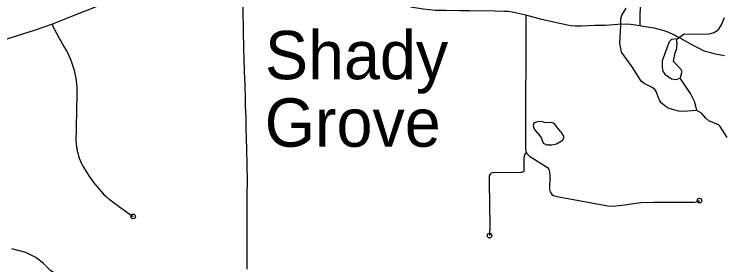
# Model space of a CAD drawing. Extents: x -19 to 366, y -4 to 359.
# Drawn here: x 143.314 to 144.78, y 191.501 to 192.02 of the extents above; entities that cross this region are included whole.
import ezdxf

# ---------------------------------------------------------------- set-up
doc = ezdxf.new("R2010")
doc.units = 0
for name, color, linetype in [('Level 24', 7, 'Continuous'), ('Level 31', 7, 'Continuous'), ('Level 32', 7, 'Continuous'), ('Level 35', 7, 'Continuous'), ('Level 60', 7, 'Continuous')]:
    doc.layers.add(name, color=color, linetype=linetype)

msp = doc.modelspace()

# ---------------------------------------------------------------- linework, layer by layer
at = {"layer": 'Level 31'}
for points in [[(143.785, 192.1059), (143.7855, 192.0918), (143.7865, 192.0521), (143.7867, 192.0267), (143.7881, 191.9466), (143.7888, 191.9291), (143.7894, 191.901)], [(143.4977, 192.041), (143.4828, 192.0352), (143.4289, 192.0136), (143.3943, 192.0002), (143.3929, 191.9996)], [(144.3723, 192.0176), (144.3536, 192.0224), (144.3441, 192.0243), (144.3355, 192.0253), (144.3281, 192.0257), (144.3077, 192.0261), (144.2556, 192.0267), (144.235, 192.0272), (144.2071, 192.0276), (144.1852, 192.0279), (144.1726, 192.0287), (144.1597, 192.0301), (144.1385, 192.0339), (144.126, 192.0374), (144.1074, 192.0433)], [(144.3723, 192.0176), (144.3714, 191.7521), (144.3715, 191.7421)], [(144.7833, 191.9338), (144.7642, 191.9375), (144.755, 191.9397), (144.7441, 191.9428), (144.7384, 191.9451), (144.7321, 191.948), (144.7186, 191.9549), (144.6915, 191.9702), (144.6833, 191.9747), (144.6799, 191.9765), (144.6682, 191.9822), (144.6585, 191.9857), (144.6478, 191.9885), (144.6379, 191.9908), (144.6143, 191.9947), (144.6071, 191.996), (144.5948, 191.998), (144.5885, 191.9989), (144.5803, 191.999), (144.5622, 191.9984), (144.5368, 191.9969), (144.527, 191.9967), (144.5149, 191.9963), (144.4873, 191.9949), (144.4811, 191.9949), (144.4743, 191.9953), (144.4659, 191.9962), (144.4584, 191.9974), (144.4353, 192.002), (144.4208, 192.0052), (144.4051, 192.009), (144.3723, 192.0176)], [(143.3929, 191.9996), (143.3568, 191.9872), (143.236, 191.9493)], [(143.3929, 191.9996), (143.3927, 191.9957), (143.4058, 191.9714), (143.4163, 191.9529), (143.4228, 191.9418), (143.4307, 191.9247), (143.4351, 191.9126), (143.4369, 191.9065), (143.4385, 191.9003), (143.4398, 191.8941), (143.4409, 191.8879), (143.4426, 191.8756), (143.4427, 191.8752), (143.4429, 191.8701), (143.443, 191.8649), (143.443, 191.8594), (143.443, 191.8519), (143.4428, 191.8421), (143.4426, 191.8331), (143.4415, 191.7741), (143.4414, 191.7669), (143.4414, 191.7611), (143.4414, 191.7581), (143.4415, 191.7558), (143.4417, 191.7526), (143.4419, 191.7505), (143.4423, 191.7474), (143.4426, 191.7445), (143.4431, 191.7418), (143.4436, 191.7384), (143.4441, 191.7364), (143.4449, 191.733), (143.4459, 191.7297), (143.4466, 191.727), (143.4482, 191.7223), (143.4502, 191.717), (143.4522, 191.7125), (143.4543, 191.708), (143.4566, 191.7037), (143.4588, 191.6999), (143.4622, 191.6946), (143.4658, 191.6892), (143.4695, 191.6837), (143.474, 191.6771), (143.4778, 191.6719), (143.4822, 191.6662), (143.4857, 191.6618), (143.4897, 191.6572), (143.4939, 191.6527), (143.4986, 191.6479), (143.5036, 191.6431), (143.5099, 191.6375), (143.5148, 191.6336), (143.521, 191.6289), (143.5279, 191.624), (143.5343, 191.6195), (143.5407, 191.615), (143.5458, 191.6114), (143.5598, 191.6017)], [(143.7894, 191.901), (143.7905, 191.8739), (143.7908, 191.8667), (143.7913, 191.8507), (143.7917, 191.8294), (143.7925, 191.8055), (143.7931, 191.7853), (143.7938, 191.7619), (143.7943, 191.7412), (143.7951, 191.7084), (143.7952, 191.673), (143.795, 191.6492), (143.7948, 191.6158), (143.7948, 191.6002), (143.7948, 191.5857), (143.7948, 191.5603), (143.7948, 191.5467), (143.7948, 191.4948), (143.7948, 191.4924)], [(144.3715, 191.7421), (144.3724, 191.7364), (144.3747, 191.7313), (144.3796, 191.7266), (144.4149, 191.7045), (144.4177, 191.7024), (144.4199, 191.6989), (144.4213, 191.6933), (144.4214, 191.6847), (144.4212, 191.6582), (144.4223, 191.6526), (144.4262, 191.647), (144.4296, 191.6448), (144.436, 191.6428), (144.4481, 191.6409), (144.5418, 191.6238), (144.5505, 191.6229), (144.5584, 191.6232), (144.5766, 191.6257), (144.5945, 191.6285), (144.6102, 191.6302), (144.6362, 191.6308), (144.7213, 191.6311), (144.728, 191.6325), (144.7314, 191.6344)], [(144.3733, 191.7343), (144.3694, 191.7294), (144.3676, 191.7228), (144.3676, 191.6988), (144.3676, 191.6961), (144.367, 191.6937), (144.3654, 191.6931), (144.3633, 191.6925), (144.3615, 191.6925), (144.3031, 191.6919), (144.3004, 191.691), (144.2983, 191.6892), (144.2964, 191.6858), (144.2964, 191.6816), (144.2964, 191.6719), (144.2973, 191.582), (144.297, 191.562)]]:
    msp.add_lwpolyline(points, dxfattribs=at)
for centre in [(144.7314, 191.6344), (143.5598, 191.6017), (144.297, 191.562)]:
    msp.add_circle(centre, 0.00473, dxfattribs=at)
at = {"layer": 'Level 32'}
msp.add_lwpolyline([(144.6088, 191.9957), (144.6097, 192.1166)], dxfattribs=at)
at = {"layer": 'Level 35'}
for points in [[(144.5922, 191.9109), (144.5702, 191.9416), (144.5666, 191.9598), (144.5687, 191.9968), (144.5688, 192.0102), (144.5704, 192.0177), (144.5798, 192.0325)], [(144.6853, 191.9687), (144.6994, 191.9795), (144.7121, 191.9784), (144.7515, 191.9795), (144.7617, 191.9823), (144.7704, 191.9886), (144.7771, 191.9976), (144.7829, 192.0128)], [(144.6906, 191.8874), (144.6921, 191.8889), (144.6948, 191.899), (144.6946, 191.9022), (144.6927, 191.9062), (144.6795, 191.9198), (144.6777, 191.9233), (144.681, 191.9397), (144.6847, 191.949), (144.6854, 191.9619), (144.6838, 191.9636), (144.6853, 191.9687), (144.6736, 191.9673), (144.6683, 191.9625), (144.6541, 191.9233), (144.654, 191.9095), (144.6558, 191.9021), (144.6598, 191.8957), (144.6735, 191.8865), (144.6841, 191.8851), (144.6906, 191.8874)], [(144.7883, 191.765), (144.7742, 191.7876), (144.7704, 191.791), (144.7504, 191.7997), (144.7443, 191.805), (144.7352, 191.815), (144.7308, 191.8183), (144.7256, 191.8206), (144.697, 191.819), (144.6876, 191.8195), (144.6689, 191.8247), (144.6623, 191.828), (144.6524, 191.8367), (144.6477, 191.8438), (144.6415, 191.8603), (144.6389, 191.8639), (144.6331, 191.8682), (144.617, 191.8769), (144.6105, 191.8816), (144.5922, 191.9109)], [(144.7256, 191.8206), (144.7217, 191.8382), (144.7126, 191.8557), (144.6925, 191.8855), (144.6906, 191.8874)], [(144.4439, 191.7773), (144.4305, 191.7936), (144.4244, 191.7957), (144.4132, 191.795), (144.4041, 191.798), (144.3965, 191.7972), (144.3895, 191.7952), (144.3869, 191.7918), (144.3879, 191.7861), (144.3899, 191.7814), (144.3962, 191.7738)], [(144.4439, 191.7773), (144.4499, 191.7676), (144.4503, 191.7631), (144.4469, 191.7579), (144.4392, 191.7529), (144.4352, 191.751), (144.425, 191.7487), (144.4159, 191.7493), (144.4085, 191.7523), (144.4046, 191.7642), (144.3994, 191.7712), (144.3962, 191.7738)], [(143.658, 191.3218), (143.6516, 191.3327), (143.6348, 191.351), (143.6296, 191.3604), (143.6278, 191.3671), (143.6415, 191.366), (143.6399, 191.3704), (143.6302, 191.3807), (143.6121, 191.3956), (143.603, 191.4127), (143.5938, 191.4206), (143.5634, 191.4373), (143.5233, 191.4506), (143.5039, 191.4538), (143.4851, 191.4628), (143.4556, 191.4739), (143.4097, 191.4834), (143.397, 191.4842), (143.3894, 191.4893), (143.3741, 191.504), (143.3584, 191.5167), (143.3377, 191.527), (143.3088, 191.5343)]]:
    msp.add_lwpolyline(points, dxfattribs=at)
at = {"layer": 'Level 60'}
for points in [[(146.7783, 1.697), (146.5788, 10.3131), (146.3785, 18.9294), (146.1776, 27.5458), (145.9759, 36.1624), (145.7736, 44.7791), (145.5705, 53.396), (145.3668, 62.013), (145.1624, 70.6301), (144.9572, 79.2474), (144.7514, 87.8648), (144.5449, 96.4823), (144.3377, 105.1), (144.1299, 113.7179), (143.9213, 122.3359), (143.712, 130.954), (143.5021, 139.5723), (143.2915, 148.1907), (143.0802, 156.8092), (142.8682, 165.4279), (142.6555, 174.0468), (142.4422, 182.6658), (142.2282, 191.2849), (142.0135, 199.9042), (141.7981, 208.5236), (141.582, 217.1432), (141.3653, 225.7629), (141.1479, 234.3828), (140.9298, 243.0028), (140.711, 251.623), (140.4916, 260.2433), (140.2715, 268.8638), (140.0508, 277.4844), (139.8293, 286.1051), (139.6072, 294.726), (139.3845, 303.3471), (139.161, 311.9683), (138.937, 320.5896), (138.7122, 329.2111), (138.4868, 337.8328), (138.2607, 346.4546)], [(0, 189.5162), (7.1121, 189.5206), (14.2243, 189.5339), (21.3364, 189.556), (28.4484, 189.5869), (35.5605, 189.6267), (42.6725, 189.6754), (49.7844, 189.7329), (56.8962, 189.7992), (64.0079, 189.8744), (71.1196, 189.9584), (78.2311, 190.0512), (85.3425, 190.1529), (92.4538, 190.2635), (99.5649, 190.3829), (106.6759, 190.5111), (113.7867, 190.6482), (120.8974, 190.7941), (128.0078, 190.9489), (135.1181, 191.1125), (142.2282, 191.2849), (149.338, 191.4662), (156.4476, 191.6563), (163.5569, 191.8553), (170.666, 192.0631), (177.7749, 192.2798), (184.8835, 192.5053), (191.9917, 192.7396), (199.0997, 192.9828), (206.2074, 193.2348), (213.3147, 193.4956), (220.4218, 193.7653), (227.5285, 194.0438), (234.6348, 194.3312), (241.7408, 194.6274), (248.8464, 194.9324), (255.9516, 195.2463), (263.0564, 195.569), (270.1608, 195.9005), (277.2648, 196.2409), (284.3683, 196.5901), (291.4715, 196.9481), (298.5741, 197.315), (305.6763, 197.6907), (312.7781, 198.0753), (319.8793, 198.4686), (326.9801, 198.8708), (334.0804, 199.2818), (341.1801, 199.7017)]]:
    msp.add_spline(points, degree=3, dxfattribs=at)

# ---------------------------------------------------------------- texts
at = {"layer": 'Level 24'}
for s, p in [('Shady', (143.8323, 191.8854)), ('Grove', (143.8319, 191.7458))]:
    msp.add_text(s, height=0.1, dxfattribs=at).set_placement(p)

doc.saveas('drawing.dxf')
